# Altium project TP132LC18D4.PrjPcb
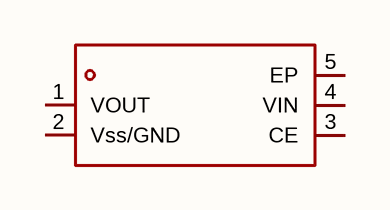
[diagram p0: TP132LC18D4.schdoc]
1 sheet, 1 parts. Net scope: global (net labels, ports and power ports of the same name join across sheets).

## Sheet TP132LC18D4.schdoc
size 127 x 101 mm

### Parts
U?  tp132lc18d4  [DFN-4_L1.0-W1.0-P0.65-BL-EP]  (value not drawn)

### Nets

Not connected (* = marked no-connect by the designer): U? 1(VOUT) 2(Vss/GND) 3(CE) 4(VIN) 5(EP)

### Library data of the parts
U? = tp132lc18d4: 输出极性:正极;工作电压:7V;输出电压:1.8V;输出电流:300mA;电源纹波抑制比(PSRR):70dB@(1kHz);输出类型:固定;; Manufacturer: TECH PUBLIC(台舟); AddInBom: yes; ModelId: bb5c60478e114cecafb4cacfcccae5cc; ModelName: DFN-4_L1.0-W1.0-H0.5-P0.65-BL-EP; ModelTransform: 40.1574,40.1574,0,0,0,0,0.18,0.02,0; Output Configuration: 正极; Voltage - Supply: 7V; Output Voltage: 1.8V; Output Current: 300mA; Voltage Dropout: 450uV; standby current: 800nA; Output Type: 固定; Number of Outputs: 1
